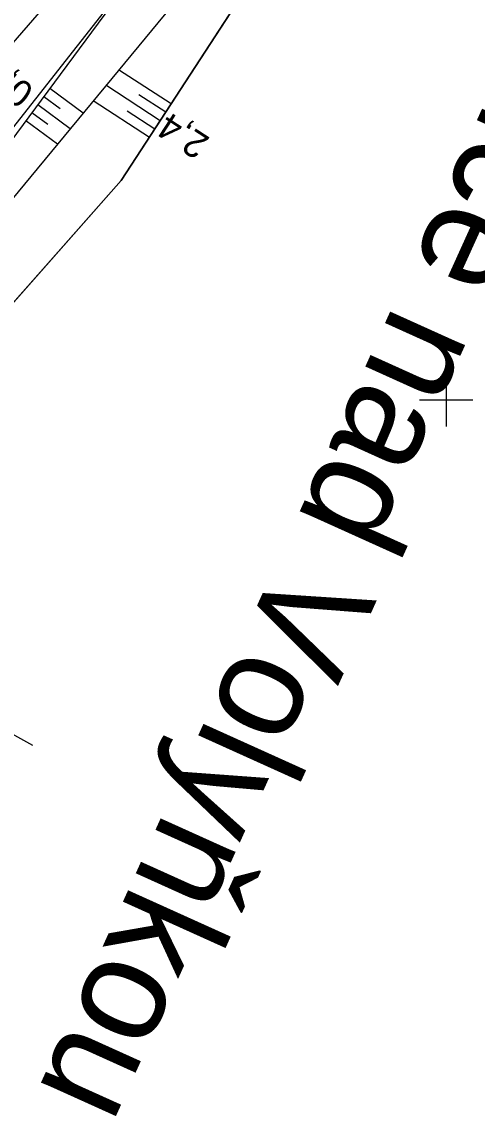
# Model space of a CAD drawing. Extents: x -795094 to -794639, y -1135368 to -1134681.
# Drawn here: x -794831.7 to -794797.7, y -1135053.6 to -1134971.7 of the extents above; entities that cross this region are included whole.
import ezdxf

# ---------------------------------------------------------------- set-up
doc = ezdxf.new("R2010")
doc.units = 0
for name, color, linetype in [('0381KM005-009P - Vrstva 2', 7, 'Continuous'), ('0381KM005-009P - Vrstva 23', 7, 'Continuous'), ('0381KM005-009P - Vrstva 48', 7, 'Continuous'), ('0381KM005-009P - Vrstva 49', 7, 'Continuous'), ('0381KM005-009P - Vrstva 51', 7, 'Continuous'), ('krizky_1000 - Vrstva 1', 7, 'Continuous')]:
    doc.layers.add(name, color=color, linetype=linetype)

msp = doc.modelspace()

# ---------------------------------------------------------------- linework, layer by layer
at = {"layer": '0381KM005-009P - Vrstva 2'}
msp.add_line((-794830.917, -1135025.882), (-794874.769, -1135001.818), dxfattribs=at)
at = {"layer": '0381KM005-009P - Vrstva 48'}
for p, q in [((-794820.559, -1134977.843), (-794824.489, -1134975.286)), ((-794829.639, -1134976.677), (-794827.152, -1134978.519)), ((-794821.377, -1134979.101), (-794825.449, -1134976.451)), ((-794830.086, -1134977.28), (-794828.857, -1134978.19)), ((-794820.968, -1134978.472), (-794822.969, -1134977.17)), ((-794830.532, -1134977.883), (-794828.106, -1134979.679)), ((-794822.195, -1134980.358), (-794826.408, -1134977.616)), ((-794831.424, -1134979.089), (-794829.061, -1134980.838)), ((-794830.978, -1134978.486), (-794829.781, -1134979.372)), ((-794821.786, -1134979.729), (-794823.857, -1134978.381))]:
    msp.add_line(p, q, dxfattribs=at)
at = {"layer": '0381KM005-009P - Vrstva 49'}
for p, q in [((-794790.5, -1134931.648), (-794824.29, -1134983.577)), ((-794819.082, -1134962.417), (-794848.099, -1135001.612)), ((-794819.559, -1134969.298), (-794845.522, -1135000.83)), ((-794837.373, -1134998.386), (-794824.29, -1134983.577))]:
    msp.add_line(p, q, dxfattribs=at)
at = {"layer": '0381KM005-009P - Vrstva 51'}
for p, q in [((-794828.146, -1134968.345), (-794846.073, -1134989.059)), ((-794824.295, -1134969.269), (-794848.049, -1134999.571))]:
    msp.add_line(p, q, dxfattribs=at)
msp.add_lwpolyline([(-794871.739, -1135021.338), (-794845.859, -1135006.134), (-794837.373, -1134998.386), (-794824.29, -1134983.577), (-794790.5, -1134931.648), (-794766.188, -1134894.559)], dxfattribs=at)
at = {"layer": 'krizky_1000 - Vrstva 1'}
for points in [[(-794800, -1134998), (-794800, -1135002)], [(-794802, -1135000), (-794798, -1135000)]]:
    msp.add_lwpolyline(points, dxfattribs=at)

# ---------------------------------------------------------------- texts
at = {"layer": '0381KM005-009P - Vrstva 23'}
msp.add_text('žst. Strunkovice nad Volyňkou', height=8, rotation=245.66299, dxfattribs=at).set_placement((-794771.538, -1134921.216))
at = {"layer": '0381KM005-009P - Vrstva 48'}
for s, rotation, p in [('0,4', 143.48656, (-794830.703, -1134976.676)), ('2,4', 146.9481, (-794817.586, -1134980.427))]:
    msp.add_text(s, height=2, rotation=rotation, dxfattribs=at).set_placement(p)

doc.saveas('drawing.dxf')
